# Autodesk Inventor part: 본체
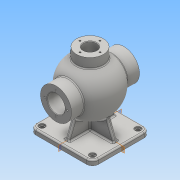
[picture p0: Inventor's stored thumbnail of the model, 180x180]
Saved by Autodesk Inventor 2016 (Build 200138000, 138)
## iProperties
Created: 2017-01
Part Number: 본체
Material: 일반
Document SubType Name: Modeling
Designer: Administrator
Density: 1 g/cm^3
Appearance: 기본값
Author: Administrator
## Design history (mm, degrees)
sketch "스케치1"
  geometry: L1 (0, 0)-(125, 0); L2 (125, 0)-(125, 115); L3 (125, 115)-(0, 115); L4 (0, 115)-(0, 0)
  constraints: 8 end point, 2 parallel, 1 horizontal, 1 perpendicular
  dimensions: "d0" = 125 distance of L3.end L2.end; "d1" = 115 distance of L2.end L1.end
extrude "돌출1" new body sketch "스케치1" distance "d2" = 10; taper "d3" = 0 deg
fillet "모깎기1" dims "d4" = 12
sketch "스케치2"
  geometry: L1 (62.5, 153.628)-(62.5, -34.735); L2 (-66.186, 57.5)-(185.77, 57.5); L3 (113, 115)-(12, 115) reference; L4 (0, 103)-(0, 12) reference; A1 r 12 centre (12, 103) between (12, 115) and (0, 103) reference; 2 further points
  constraints: 4 end point, 1 coincident, 1 horizontal, 1 vertical
  dimensions: "d5" = 57.5 distance between parallel lines of L2 L3; "d6" = 62.5 distance between parallel lines of L4 L1
hole "구멍1" sketch "스케치2" at (12, 103) diameter "d7" = 8; stored, may be unused: countersink angle "d11" = 90 deg, drill point angle "d13" = 118 deg; dims "d8" = 6, "d9" = 12, "d10" = 3, "d12" = 8
fillet "모깎기2" dims "d20" = 3
node "작업 평면3"
node "작업 평면4"
sketch "스케치4"
  geometry: L1 (85, -45.352)-(85, 154.07); L2 (0, 0)-(0, 91) reference; L3 (85, -22.5)-(116, -22.5); L4 (116, -22.5)-(116, 2.512); L5 (85, 113.5)-(116, 113.5); L6 (116, 113.5)-(116, 88.488); L7 (0, 91)-(0, 0) reference; L8 (0, 45.5)-(153.3, 45.5); L9 (85, -22.5)-(85, 113.5); A1 r 53 centre (85, 45.5) between (116, 2.512) and (116, 88.488); 1 further point
  constraints: 14 end point, 4 perpendicular, 4 point on line, 2 point on circle, 1 centre point, 1 collinear, 1 horizontal, 1 midpoint, 1 vertical
  dimensions: "d21" = 85 distance between parallel lines of L2 L1; "d22" = 31 horizontal distance of L1.start L3.end; "d23" = 31 distance from line of L1 L5.end; "d24" = 136 distance of L5.end L3.end; "d25" = 68 distance from line of L8 L5.end; "d26" = 106 diameter of A1
revolve "회전1" sketch "스케치4" stored, may be unused: angle "d27" = 90 deg
node "작업 평면5"
sketch "스케치5"
  geometry: C1 r 27 at (-62.5, 57.5); C2 r 13 at (-62.5, 57.5); 1 further point
  constraints: 2 centre point, 1 coincident
  dimensions: "d29" = 54 diameter of C1; "d32" = 26 diameter of C2
extrude "돌출2" join sketch "스케치5" stored distance "d30" = 10; taper "d31" = 0 deg
extrude "돌출3" cut sketch "스케치5" distance "d33" = 65; taper "d34" = 0 deg
sketch "스케치6"
  geometry: L1 (85, -54.348)-(85, 163.047); L2 (0, 91)-(0, 103) reference; L3 (0, 91)-(0, 0) reference; L4 (0, 45.5)-(163.738, 45.5); L5 (54, -22.5)-(116, -22.5) reference; L6 (102.5, -22.5)-(102.5, 6.222); L7 (54, 113.5)-(116, 113.5) reference; L8 (85, 58.5)-(85, 32.5) reference; L9 (102.5, -22.5)-(85, -22.5); L10 (85, -22.5)-(85, 113.5); L11 (103.5, 97.5)-(102.5, 97.5); L12 (103.5, 95.75)-(102.5, 95.75); L13 (103.5, 95.75)-(103.5, 97.5); L14 (102.5, 113.5)-(102.5, 97.5); L15 (102.5, 95.75)-(102.5, 84.778); A1 r 43 centre (85, 45.5) between (102.5, 6.222) and (102.5, 84.778); 1 further point
  constraints: 20 end point, 5 vertical, 4 midpoint, 2 perpendicular, 2 point on circle, 2 point on line, 1 centre point, 1 horizontal
  dimensions: "d35" = 85 distance between parallel lines of L2 L1; "d36" = 17.5 distance from line of L1 L6.start; "d37" = 17.5 distance from line of L1 L14.start; "d38" = 86 diameter of A1; "d39" = 16 distance between parallel lines of L7 L11; "d40" = 1.75 distance between parallel lines of L12 L11; "d41" = 18.5 distance between parallel lines of L1 L13
revolve "회전2" sketch "스케치6" stored, may be unused: angle "d42" = 90 deg
sketch "스케치7"
  geometry: L1 (10, 0)-(10, 91) reference; L2 (10, -2)-(44.109, 11.781); L3 (10, -2)-(72.654, -2); L4 (0, -12)-(7, -12) reference; L5 (10, 93)-(44.109, 79.219); L6 (10, 93)-(58.222, 93); L7 (7, 103)-(0, 103) reference; L8 (10, -2)-(10, 93); L9 (10, 97)-(10, 85) reference; A1 r 53 centre (85, 45.5) between (44.109, 79.219) and (44.109, 11.781)
  constraints: 10 end point, 2 horizontal, 2 point on circle, 2 point on line, 1 centre point, 1 collinear
  dimensions: "d43" = 22 deg angle of L3 L2; "d44" = 10 distance from line of L4 L2.start; "d45" = 22 deg angle of L5 L6; "d46" = 10 distance from line of L7 L5.start
extrude "돌출4" join sketch "스케치7" stored distance "d47" = 8; taper "d48" = 0 deg
sketch "스케치8"
  geometry: L1 (0, 10)-(101, 10) reference; L2 (-2, 10)-(13.121, 47.426); L3 (-12, 0)-(-12, 7) reference; L4 (103, 10)-(87.879, 47.426); L5 (113, 7)-(113, 0) reference; L6 (-2, 10)-(103, 10); L7 (101, 7)-(0, 7) reference; A1 r 53 centre (50.5, 85) between (23.5, 130.607) and (77.5, 130.607) reference; A2 r 53 centre (50.5, 85) between (13.121, 47.426) and (87.879, 47.426)
  constraints: 6 end point, 4 point on circle, 2 point on line, 1 centre point, 1 parallel
  dimensions: "d49" = 68 deg angle of L1 L2; "d50" = 10 distance from line of L2.start L3; "d51" = 68 deg angle of L1 L4; "d52" = 10 distance from line of L5 L4.start
extrude "돌출5" join sketch "스케치8" stored distance "d53" = 8; taper "d54" = 0 deg
sketch "스케치9"
  geometry: 2 further points
hole "구멍2" sketch "스케치9" at (0, 22.5) diameter "d57" = 3.242; stored, may be unused: countersink angle "d61" = 90 deg, drill point angle "d63" = 118 deg; dims "d58" = 12, "d59" = 4, "d60" = 3, "d62" = 15
sketch "스케치10"
  geometry: C1 r 17.5 at (0, 0) reference; 2 further points
hole "구멍3" sketch "스케치10" at (0, -24) diameter "d70" = 3.242; stored, may be unused: countersink angle "d74" = 90 deg, drill point angle "d76" = 118 deg; dims "d71" = 16, "d72" = 4, "d73" = 3, "d75" = 19
sketch "스케치11"
  geometry: 2 further points
hole "구멍4" sketch "스케치11" at (0.113, -20) diameter "d81" = 3.242; stored, may be unused: countersink angle "d85" = 90 deg, drill point angle "d87" = 118 deg; dims "d82" = 9, "d83" = 4, "d84" = 3, "d86" = 11
chamfer "모따기1" distance "d91" = 1; stored, may be unused: second distance "d92" = 2, angle "d93" = 45 deg
chamfer "모따기2" distance "d94" = 1; stored, may be unused: second distance "d95" = 2, angle "d96" = 45 deg
fillet "모깎기3" dims "d97" = 3
fillet "모깎기4" dims "d98" = 3
sketch "스케치13"
  geometry: L1 (135.763, 51.682)-(135.763, 39.318); L2 (135.763, 39.318)-(144.237, 39.318); L3 (144.237, 39.318)-(144.237, 51.682); L4 (144.237, 51.682)-(135.763, 51.682); L5 (150, 18.5)-(150, 72.5) reference; 3 further points
  constraints: 2 midpoint, 2 other
  dimensions: "d99" = 10 distance from line of L5 point (140, 39.318); "d101" = 27 vertical distance of L5.end point (144.237, 45.5)
feature "엠보싱1" sketch "스케치13" dims "d0" = 125, "d1" = 115, "d13" = 118 deg, "d102" = 0.5, "d103" = 0
node "솔리드1"
pattern_linear "직사각형 패턴1" dims "d16" = 91, "d19" = 101
pattern_circular "원형 패턴1" dims angle "d65" = 360 deg
pattern_circular "원형 패턴2" dims angle "d78" = 360 deg
pattern_circular "원형 패턴3" dims angle "d89" = 360 deg
